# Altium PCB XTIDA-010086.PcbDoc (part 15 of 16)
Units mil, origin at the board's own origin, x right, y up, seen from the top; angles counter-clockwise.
Board outline 14763.78 x 8267.72 mil, 6 copper layers (Top Layer, GND Layer, Signal Layer 1, Signal Layer 2, Power Layer, Bottom Layer), stack 62 mil thick; 1933 components, 1002 nets, 4886 pads, 6482 vias.
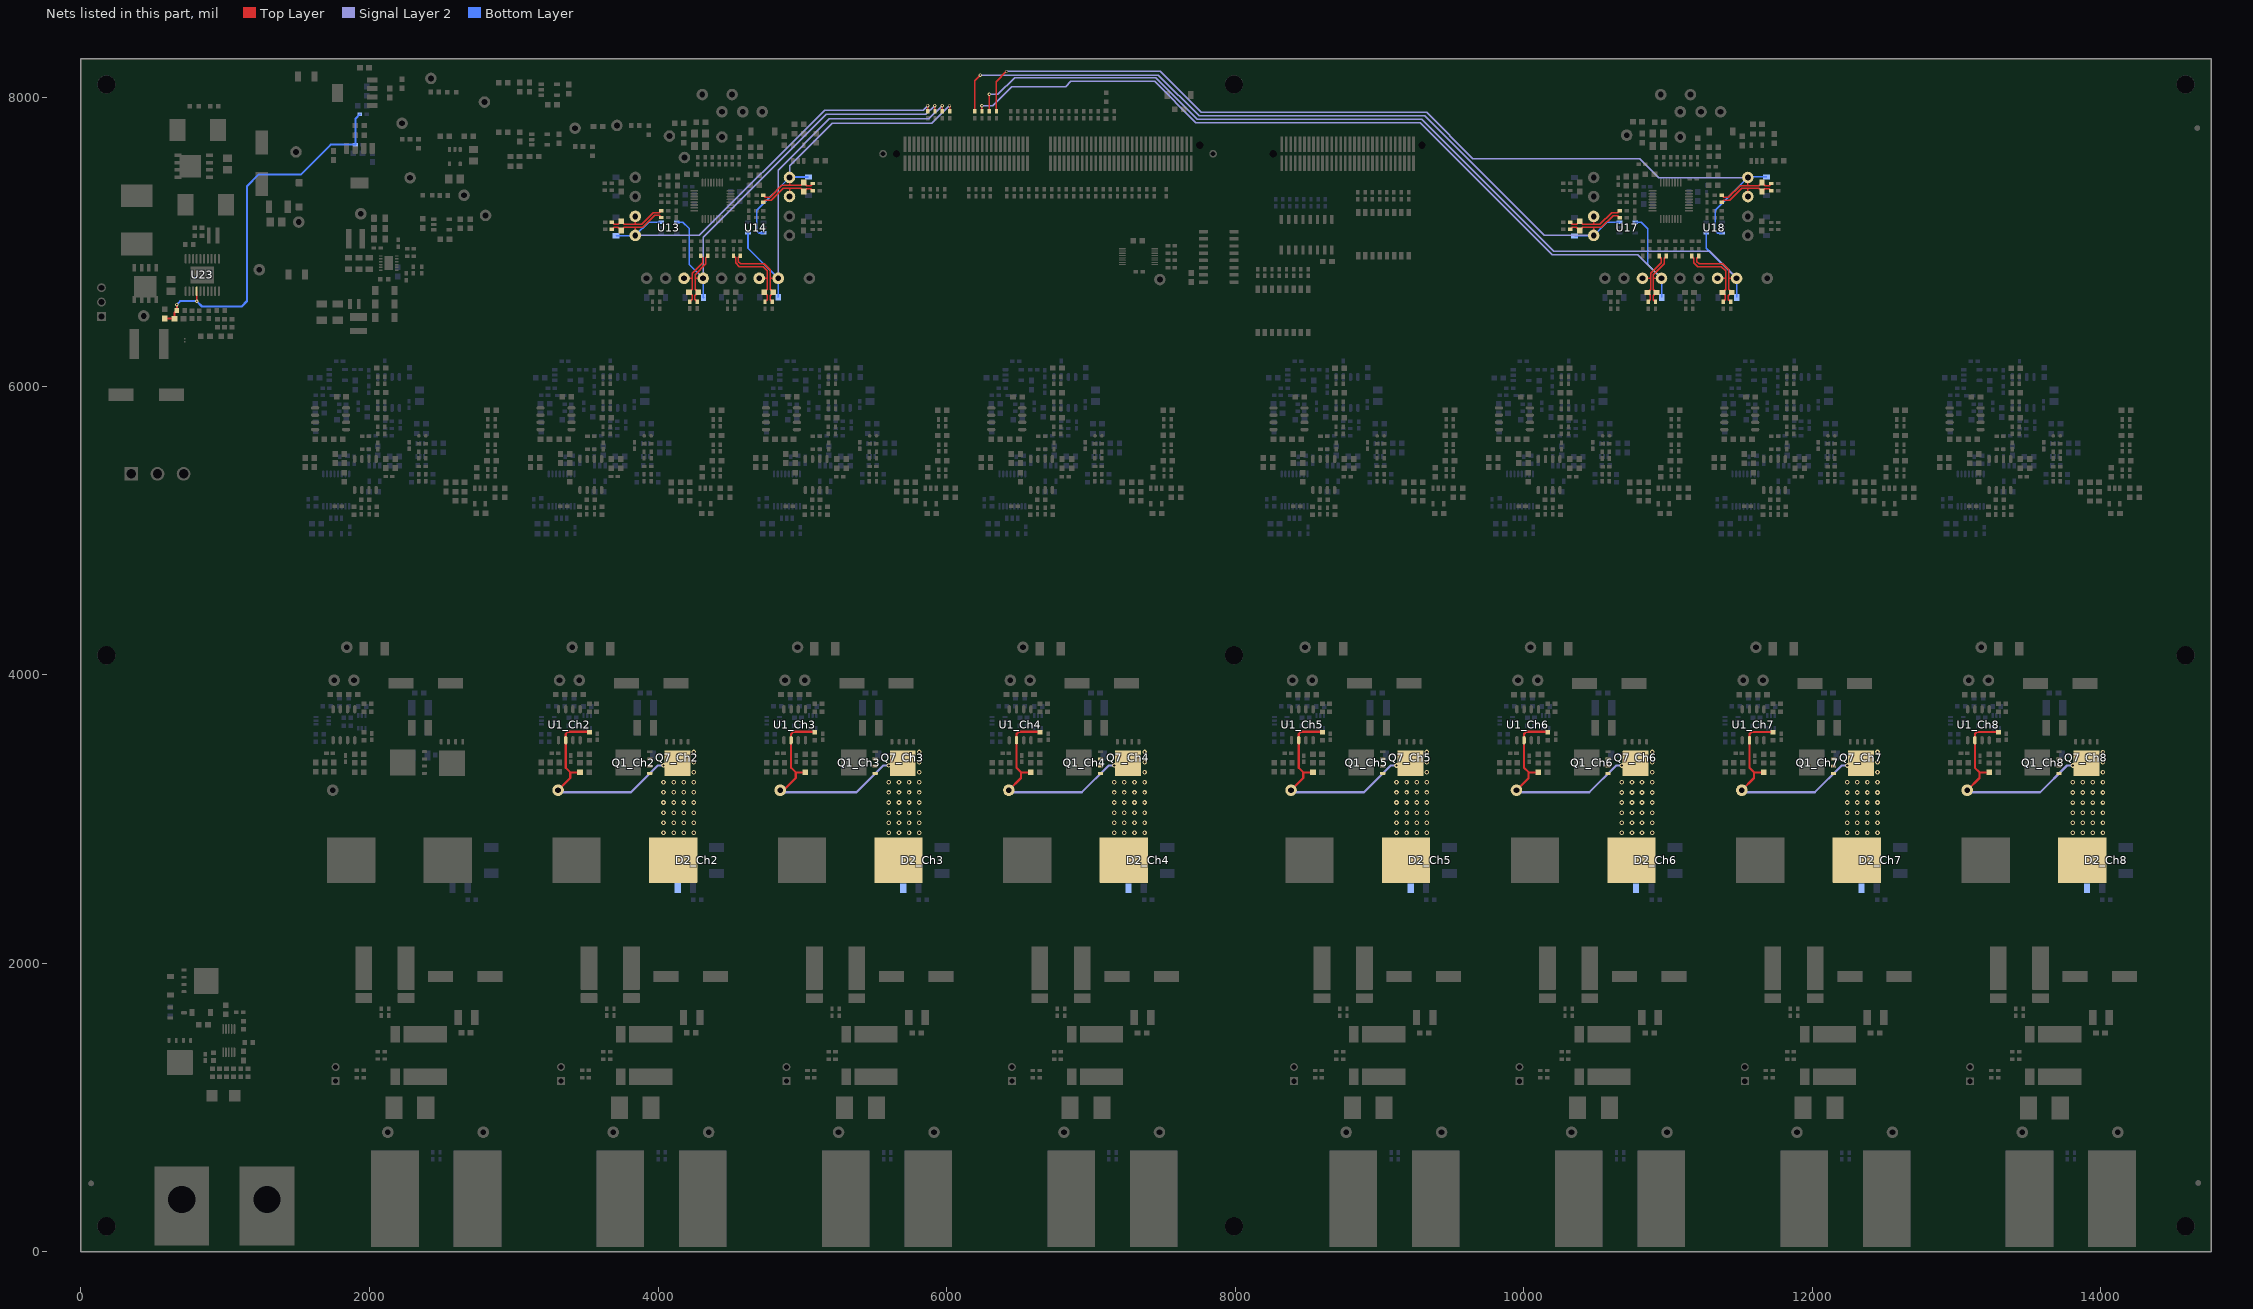
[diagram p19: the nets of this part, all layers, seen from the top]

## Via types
v1: diameter 32, hole 16, Top Layer to Bottom Layer, tented both sides, 4685 vias
v2: diameter 24, hole 12, Top Layer to Bottom Layer, tented both sides, 1013 vias
v3: diameter 32, hole 16, Top Layer to Bottom Layer, 728 vias
v4: diameter 19.68, hole 7.87, Top Layer to Bottom Layer, 40 vias
v5: diameter 214.57, hole 140, Top Layer to Bottom Layer, 16 vias

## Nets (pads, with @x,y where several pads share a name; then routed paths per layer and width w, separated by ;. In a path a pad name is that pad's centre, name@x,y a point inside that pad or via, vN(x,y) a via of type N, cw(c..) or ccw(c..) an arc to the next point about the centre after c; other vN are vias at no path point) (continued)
SW_Ch2: C1_Ch2.2 C2_Ch2.1 D2_Ch2.4 L2_Ch2.1 Q1_Ch2.1 Q1_Ch2.2 Q1_Ch2.3 Q7_Ch2.5 Q7_Ch2.6 Q7_Ch2.7 Q7_Ch2.8 Q7_Ch2.9@4134,3385.39 R9_Ch2.1 R18_Ch2.1 TP2_Ch2.1 U1_Ch2.6 | length 1490.1
  Top Layer w15: TP2_Ch2.1@3307.39,3199.23 3392.16,3283.99 3392.16,3322.99 ; R18_Ch2.1@3459.37,3322.99 3392.16,3322.99 ; C1_Ch2.2@3524.33,3601.79 3522.08,3604.04 3375.11,3604.04 3360.37,3589.29 U1_Ch2.6@3360.37,3545.71 3360.37,3354.78 3392.16,3322.99
  Signal Layer 2 w15: TP2_Ch2.1@3307.39,3199.23 3321.7,3184.92 3813,3184.92 3999,3370.92 v1(4038,3370.92)
  other v1: 4038,2903.92 4108,2903.92 4178,2903.92 4248,2903.92 4038,2973.92 4108,2973.92 4178,2973.92 4248,2973.92 4038,3043.92 4108,3043.92 4178,3043.92 4248,3043.92 4038,3113.92 4108,3113.92 4178,3113.92 4248,3113.92 4038,3183.92 4108,3183.92 4178,3183.92 4248,3183.92 4038,3253.92 4108,3253.92 4178,3253.92 4248,3253.92 4248,3323.92 4248,3393.92 4248,3463.92
SW_Ch3: C1_Ch3.2 C2_Ch3.1 D2_Ch3.4 L2_Ch3.1 Q1_Ch3.1 Q1_Ch3.2 Q1_Ch3.3 Q7_Ch3.5 Q7_Ch3.6 Q7_Ch3.7 Q7_Ch3.8 Q7_Ch3.9@5696,3385.31 R9_Ch3.1 R18_Ch3.1 TP2_Ch3.1 U1_Ch3.6 | length 1490.1
  Top Layer w15: TP2_Ch3.1@4869.39,3199.15 4954.16,3283.91 4954.16,3322.91 ; R18_Ch3.1@5021.37,3322.91 4954.16,3322.91 ; C1_Ch3.2@5086.33,3601.71 5084.08,3603.96 4937.11,3603.96 4922.37,3589.21 U1_Ch3.6@4922.37,3545.63 4922.37,3354.7 4954.16,3322.91
  Signal Layer 2 w15: TP2_Ch3.1@4869.39,3199.15 4883.7,3184.84 5375,3184.84 5561,3370.84 v1(5600,3370.84)
  other v1: 5600,2903.84 5670,2903.84 5740,2903.84 5810,2903.84 5600,2973.84 5670,2973.84 5740,2973.84 5810,2973.84 5600,3043.84 5670,3043.84 5740,3043.84 5810,3043.84 5600,3113.84 5670,3113.84 5740,3113.84 5810,3113.84 5600,3183.84 5670,3183.84 5740,3183.84 5810,3183.84 5600,3253.84 5670,3253.84 5740,3253.84 5810,3253.84 5810,3323.84 5810,3393.84 5810,3463.84
SW_Ch4: C1_Ch4.2 C2_Ch4.1 D2_Ch4.4 L2_Ch4.1 Q1_Ch4.1 Q1_Ch4.2 Q1_Ch4.3 Q7_Ch4.5 Q7_Ch4.6 Q7_Ch4.7 Q7_Ch4.8 Q7_Ch4.9@7258,3385.24 R9_Ch4.1 R18_Ch4.1 TP2_Ch4.1 U1_Ch4.6 | length 1490.1
  Top Layer w15: TP2_Ch4.1@6431.39,3199.07 6516.16,3283.83 6516.16,3322.83 ; R18_Ch4.1@6583.37,3322.83 6516.16,3322.83 ; C1_Ch4.2@6648.33,3601.63 6646.08,3603.88 6499.11,3603.88 6484.37,3589.14 U1_Ch4.6@6484.37,3545.55 6484.37,3354.62 6516.16,3322.83
  Signal Layer 2 w15: TP2_Ch4.1@6431.39,3199.07 6445.7,3184.76 6937,3184.76 7123,3370.76 v1(7162,3370.76)
  other v1: 7162,2903.76 7232,2903.76 7302,2903.76 7372,2903.76 7162,2973.76 7232,2973.76 7302,2973.76 7372,2973.76 7162,3043.76 7232,3043.76 7302,3043.76 7372,3043.76 7162,3113.76 7232,3113.76 7302,3113.76 7372,3113.76 7162,3183.76 7232,3183.76 7302,3183.76 7372,3183.76 7162,3253.76 7232,3253.76 7302,3253.76 7372,3253.76 7372,3323.76 7372,3393.76 7372,3463.76
SW_Ch5: C1_Ch5.2 C2_Ch5.1 D2_Ch5.4 L2_Ch5.1 Q1_Ch5.1 Q1_Ch5.2 Q1_Ch5.3 Q7_Ch5.5 Q7_Ch5.6 Q7_Ch5.7 Q7_Ch5.8 Q7_Ch5.9@9213.7,3385.16 R9_Ch5.1 R18_Ch5.1 TP2_Ch5.1 U1_Ch5.6 | length 1490.1
  Top Layer w15: TP2_Ch5.1@8387.09,3198.99 8471.86,3283.76 8471.86,3322.75 ; R18_Ch5.1@8539.07,3322.75 8471.86,3322.75 ; C1_Ch5.2@8604.03,3601.55 8601.78,3603.8 8454.81,3603.8 8440.07,3589.06 U1_Ch5.6@8440.07,3545.47 8440.07,3354.54 8471.86,3322.75
  Signal Layer 2 w15: TP2_Ch5.1@8387.09,3198.99 8401.4,3184.69 8892.7,3184.69 9078.7,3370.69 v1(9117.7,3370.69)
  other v1: 9117.7,2903.69 9187.7,2903.69 9257.7,2903.69 9327.7,2903.69 9117.7,2973.69 9187.7,2973.69 9257.7,2973.69 9327.7,2973.69 9117.7,3043.69 9187.7,3043.69 9257.7,3043.69 9327.7,3043.69 9117.7,3113.69 9187.7,3113.69 9257.7,3113.69 9327.7,3113.69 9117.7,3183.69 9187.7,3183.69 9257.7,3183.69 9327.7,3183.69 9117.7,3253.69 9187.7,3253.69 9257.7,3253.69 9327.7,3253.69 9327.7,3323.69 9327.7,3393.69 9327.7,3463.69
SW_Ch6: C1_Ch6.2 C2_Ch6.1 D2_Ch6.4 L2_Ch6.1 Q1_Ch6.1 Q1_Ch6.2 Q1_Ch6.3 Q7_Ch6.5 Q7_Ch6.6 Q7_Ch6.7 Q7_Ch6.8 Q7_Ch6.9@10775.7,3385.08 R9_Ch6.1 R18_Ch6.1 TP2_Ch6.1 U1_Ch6.6 | length 1490.1
  Top Layer w15: TP2_Ch6.1@9949.09,3198.91 10033.86,3283.68 10033.86,3322.68 ; R18_Ch6.1@10101.07,3322.68 10033.86,3322.68 ; C1_Ch6.2@10166.03,3601.47 10163.78,3603.72 10016.81,3603.72 10002.07,3588.98 U1_Ch6.6@10002.07,3545.39 10002.07,3354.46 10033.86,3322.68
  Signal Layer 2 w15: TP2_Ch6.1@9949.09,3198.91 9963.4,3184.61 10454.7,3184.61 10640.7,3370.61 v1(10679.7,3370.61)
  other v1: 10679.7,2903.61 10749.7,2903.61 10819.7,2903.61 10889.7,2903.61 10679.7,2973.61 10749.7,2973.61 10819.7,2973.61 10889.7,2973.61 10679.7,3043.61 10749.7,3043.61 10819.7,3043.61 10889.7,3043.61 10679.7,3113.61 10749.7,3113.61 10819.7,3113.61 10889.7,3113.61 10679.7,3183.61 10749.7,3183.61 10819.7,3183.61 10889.7,3183.61 10679.7,3253.61 10749.7,3253.61 10819.7,3253.61 10889.7,3253.61 10889.7,3323.61 10889.7,3393.61 10889.7,3463.61
SW_Ch7: C1_Ch7.2 C2_Ch7.1 D2_Ch7.4 L2_Ch7.1 Q1_Ch7.1 Q1_Ch7.2 Q1_Ch7.3 Q7_Ch7.5 Q7_Ch7.6 Q7_Ch7.7 Q7_Ch7.8 Q7_Ch7.9@12337.7,3385 R9_Ch7.1 R18_Ch7.1 TP2_Ch7.1 U1_Ch7.6 | length 1490.1
  Top Layer w15: TP2_Ch7.1@11511.09,3198.83 11595.86,3283.6 11595.86,3322.6 ; R18_Ch7.1@11663.07,3322.6 11595.86,3322.6 ; C1_Ch7.2@11728.03,3601.39 11725.78,3603.64 11578.81,3603.64 11564.07,3588.9 U1_Ch7.6@11564.07,3545.31 11564.07,3354.38 11595.86,3322.6
  Signal Layer 2 w15: TP2_Ch7.1@11511.09,3198.83 11525.4,3184.53 12016.7,3184.53 12202.7,3370.53 v1(12241.7,3370.53)
  other v1: 12241.7,2903.53 12311.7,2903.53 12381.7,2903.53 12451.7,2903.53 12241.7,2973.53 12311.7,2973.53 12381.7,2973.53 12451.7,2973.53 12241.7,3043.53 12311.7,3043.53 12381.7,3043.53 12451.7,3043.53 12241.7,3113.53 12311.7,3113.53 12381.7,3113.53 12451.7,3113.53 12241.7,3183.53 12311.7,3183.53 12381.7,3183.53 12451.7,3183.53 12241.7,3253.53 12311.7,3253.53 12381.7,3253.53 12451.7,3253.53 12451.7,3323.53 12451.7,3393.53 12451.7,3463.53
SW_Ch8: C1_Ch8.2 C2_Ch8.1 D2_Ch8.4 L2_Ch8.1 Q1_Ch8.1 Q1_Ch8.2 Q1_Ch8.3 Q7_Ch8.5 Q7_Ch8.6 Q7_Ch8.7 Q7_Ch8.8 Q7_Ch8.9@13899.7,3384.92 R9_Ch8.1 R18_Ch8.1 TP2_Ch8.1 U1_Ch8.6 | length 1490.1
  Top Layer w15: TP2_Ch8.1@13073.09,3198.76 13157.86,3283.52 13157.86,3322.52 ; R18_Ch8.1@13225.07,3322.52 13157.86,3322.52 ; C1_Ch8.2@13290.03,3601.31 13287.78,3603.56 13140.81,3603.56 13126.07,3588.82 U1_Ch8.6@13126.07,3545.23 13126.07,3354.31 13157.86,3322.52
  Signal Layer 2 w15: TP2_Ch8.1@13073.09,3198.76 13087.4,3184.45 13578.7,3184.45 13764.7,3370.45 v1(13803.7,3370.45)
  other v1: 13803.7,2903.45 13873.7,2903.45 13943.7,2903.45 14013.7,2903.45 13803.7,2973.45 13873.7,2973.45 13943.7,2973.45 14013.7,2973.45 13803.7,3043.45 13873.7,3043.45 13943.7,3043.45 14013.7,3043.45 13803.7,3113.45 13873.7,3113.45 13943.7,3113.45 14013.7,3113.45 13803.7,3183.45 13873.7,3183.45 13943.7,3183.45 14013.7,3183.45 13803.7,3253.45 13873.7,3253.45 13943.7,3253.45 14013.7,3253.45 14013.7,3323.45 14013.7,3393.45 14013.7,3463.45
UVLO: R188.1 R189.1 R206.1 R207.1 R208.2 U23.4 | length 2657.8
  Top Layer w12: v2(803.12,6588.34) U23.4@803.12,6657.5
  Top Layer w15: R207.1@581.5,6468.2 648.5,6468.2 R208.2@649.01,6467.7 649.01,6507.76 R206.1@665.94,6524.7 665.94,6563.76 v2(665,6564.7)
  Bottom Layer w15: v2(665,6564.7) 688.64,6588.34 v2(803.12,6588.34) 839.76,6551.7 1114.7,6551.7 1152,6589 1152,7385 1234,7467 1526.5,7467 1732.5,7673 R188.1@1903.38,7673 1903.38,7853 R189.1@1933.38,7883
"UVP: 10.4V": C59.2 R84.1 R88.2 U11.4 | length 219.5
  Top Layer w10: U11.4@1045.02,1383.07 1045.02,1336.98 1056.35,1325.65 1056.35,1310
  Top Layer w15: 1056.35,1310 1056.35,1269.32 1107.63,1269.32 R88.2@1107.83,1269.12 C59.2@1157.33,1269.12
VoutN1: C51_Ch1.2 R74_Ch1.2 R92.1 TP10_Ch1.1 | length 462.7
  Top Layer w10: R74_Ch1.2@3680.47,7136.14 3695.7,7120.91 3724.26,7120.91 C51_Ch1.2@3744.87,7141.52 3766.37,7120.03 3842.53,7120.03 ; TP10_Ch1.1@3842.53,7176.03 3842.53,7120.03 ; R92.1@4023.49,7216.33 4009.4,7202.24 3968.54,7202.24 3886.33,7120.03 3842.53,7120.03
VoutN2: C51_Ch2.2 R74_Ch2.2 R99.1 TP10_Ch2.1 | length 432.8
  Top Layer w10: TP10_Ch2.1@4180.68,6746.7 4235.68,6746.7 ; R74_Ch2.2@4220.57,6584.65 4235.8,6599.87 4235.8,6628.43 C51_Ch2.2@4215.18,6649.05 4236.68,6670.54 4236.68,6780.67 4311.65,6855.63 4311.65,6887.68 R99.1@4297.56,6901.77
VoutN3: C51_Ch3.2 R74_Ch3.2 R104.1 TP10_Ch3.1 | length 590.8
  Top Layer w10: R104.1@4523.3,6901.77 4537.3,6887.77 4537.3,6854.86 4564.45,6827.7 4728.47,6827.7 4757.1,6799.07 4757.1,6746.7 ; TP10_Ch3.1@4701.1,6746.7 4757.1,6746.7 ; R74_Ch3.2@4741.24,6583.71 4756.47,6598.94 4756.47,6628.18 C51_Ch3.2@4735.61,6649.05 4757.1,6670.54 4757.1,6746.7
VoutN4: C51_Ch4.2 R74_Ch4.2 R116.1 TP10_Ch4.1 | length 462.7
  Top Layer w10: R116.1@4730.36,7273.89 4744.45,7287.98 4785.31,7287.98 4867.53,7370.19 4911.32,7370.19 ; TP10_Ch4.1@4911.32,7314.19 4911.32,7370.19 ; C51_Ch4.2@5008.98,7348.14 5029.59,7368.75 5058.15,7368.75 R74_Ch4.2@5073.38,7353.52 ; C51_Ch4.2@5008.98,7348.7 4987.48,7370.19 4911.32,7370.19
VoutN5: C51_Ch5.2 R74_Ch5.2 R123.1 TP10_Ch5.1 | length 462.7
  Top Layer w10: R74_Ch5.2@10322.17,7135.82 10337.4,7120.59 10365.96,7120.59 C51_Ch5.2@10386.58,7141.21 10408.07,7119.71 10484.23,7119.71 ; TP10_Ch5.1@10484.23,7175.71 10484.23,7119.71 ; R123.1@10665.19,7216.02 10651.1,7201.93 10610.24,7201.93 10528.03,7119.71 10484.23,7119.71
VoutN6: C51_Ch6.2 R74_Ch6.2 R130.1 TP10_Ch6.1 | length 432.8
  Top Layer w10: TP10_Ch6.1@10822.38,6746.39 10877.38,6746.39 ; R74_Ch6.2@10862.27,6584.33 10877.5,6599.56 10877.5,6628.12 10861.89,6643.73 C51_Ch6.2@10856.89,6648.73 10878.38,6670.23 10878.38,6780.35 10953.35,6855.32 10953.35,6887.36 R130.1@10939.26,6901.45
VoutN7: C51_Ch7.2 R74_Ch7.2 R135.1 TP10_Ch7.1 | length 589.8
  Top Layer w10: R135.1@11165,6901.45 11179,6887.45 11179,6854.54 11206.15,6827.39 11370.17,6827.39 11398.8,6798.76 11398.8,6746.39 ; TP10_Ch7.1@11342.8,6746.39 11398.8,6746.39 ; R74_Ch7.2@11382.69,6584.33 11397.92,6599.56 11397.92,6628.12 11382.31,6643.73 C51_Ch7.2@11377.31,6648.73 11398.8,6670.23 11398.8,6746.39
VoutN8: C51_Ch8.2 R74_Ch8.2 R147.1 TP10_Ch8.1 | length 462.7
  Top Layer w10: R147.1@11372.06,7273.57 11386.15,7287.67 11427.01,7287.67 11509.23,7369.88 11553.02,7369.88 ; TP10_Ch8.1@11553.02,7313.88 11553.02,7369.88 ; C51_Ch8.2@11650.68,7347.82 11671.29,7368.44 11699.85,7368.44 R74_Ch8.2@11715.08,7353.21 ; C51_Ch8.2@11650.68,7348.38 11629.18,7369.88 11553.02,7369.88
VoutP1: C51_Ch1.1 D16.2 R68_Ch1.2 R93.1 R247.1 TP9_Ch1.1 U13.3 | length 3253.5
  Top Layer w10: R68_Ch1.2@3680.47,7085.68 3695.7,7100.91 3722.5,7100.91 C51_Ch1.1@3744.87,7078.53 3766.37,7100.03 3842,7100.03 ; TP9_Ch1.1@3842.53,7044.03 3842.53,7099.5 3842,7100.03 ; R93.1@4023.49,7168.15 4009.4,7182.24 3976.82,7182.24 3894.61,7100.03 3842,7100.03 ; R247.1@5868.74,7903.54 v2@5868.74,7944.26
  Signal Layer 2 w10: TP9_Ch1.1@3842.53,7044.03 4286.03,7044.03 5154,7912 5836.48,7912 v2(5868.06,7943.58)
  Bottom Layer w12: D16.2@3710,7041.53 3840.03,7041.53 TP9_Ch1.1@3842.53,7044.03 3934.6,7136.1 U13.3@4021.87,7136.1
VoutP2: C51_Ch2.1 D20.2 R68_Ch2.2 R100.1 R248.1 TP9_Ch2.1 U13.4 | length 3366.2
  Top Layer w10: R68_Ch2.2@4271.03,6584.65 4255.8,6599.87 4255.8,6626.67 C51_Ch2.1@4278.18,6649.05 4256.68,6670.54 4256.68,6746.7 ; TP9_Ch2.1@4312.68,6746.7 4256.68,6746.7 ; R100.1@4345.74,6901.77 4331.65,6887.68 4331.65,6847.35 4256.68,6772.38 4256.68,6746.7 ; R248.1@5919.39,7903.54 v2@5919.39,7944.26
  Signal Layer 2 w10: TP9_Ch2.1@4312.68,6746.7 4312.68,7029.68 5165,7882 5857.13,7882 v2(5918.71,7943.58)
  Bottom Layer w12: U13.4@4130.13,7136.1 4172.6,7136.1 4217,7091.7 4217,6842.38 TP9_Ch2.1@4312.68,6746.7 4312.68,6616.67 D20.2@4315.18,6614.17
VoutP3: C51_Ch3.1 D22.2 R68_Ch3.2 R107.1 R251.1 TP9_Ch3.1 U14.4 | length 3235.2
  Top Layer w10: R107.1@4571.3,6901.77 4557.3,6887.77 4557.3,6863.14 4572.74,6847.7 4736.76,6847.7 4777.1,6807.36 4777.1,6670.54 C51_Ch3.1@4798.6,6649.05 4776.47,6626.92 4776.47,6598.94 R68_Ch3.2@4791.7,6583.71 ; 4778.1,6746.7 TP9_Ch3.1@4833.1,6746.7 ; R251.1@5970.03,7903.54 v2@5970.03,7944.26
  Signal Layer 2 w10: TP9_Ch3.1@4833.1,6746.7 4833.1,7496.82 5188.28,7852 5877.78,7852 v2(5969.35,7943.58)
  Bottom Layer w12: U14.4@4623.72,7061.3 4623.72,6956.08 TP9_Ch3.1@4833.1,6746.7 4833.1,6616.11 D22.2@4833.67,6615.54
VoutP4: C51_Ch4.1 D24.2 R68_Ch4.2 R117.1 R252.1 TP9_Ch4.1 U14.3 | length 2515.6
  Top Layer w10: R117.1@4730.36,7322.07 4744.45,7307.98 4777.03,7307.98 4859.24,7390.19 4911.85,7390.19 ; TP9_Ch4.1@4911.32,7446.19 TP9_Ch4.1@4911.32,7445.63 4911.32,7390.72 4911.85,7390.19 ; C51_Ch4.1@5008.98,7411.13 5031.35,7388.75 5058.15,7388.75 R68_Ch4.2@5073.38,7403.98 ; C51_Ch4.1@5008.98,7411.69 4987.48,7390.19 4911.85,7390.19 ; R252.1@6020.68,7903.54 v2@6020.68,7944.26
  Signal Layer 2 w10: TP9_Ch4.1@4911.32,7445.63 4911.32,7525.32 5208,7822 5898.42,7822 v2(6020,7943.58)
  Bottom Layer w12: U14.3@4731.99,7061.3 4698.25,7061.3 4684.85,7074.7 4684.85,7219.16 TP9_Ch4.1@4911.32,7445.63 4915.19,7449.5 D24.2@5041.93,7449.5
VoutP5: C51_Ch5.1 D26.2 R68_Ch5.2 R124.1 R255.1 TP9_Ch5.1 U17.3 | length 5792.4
  Top Layer w10: R255.1@6194.68,7903.54 6194.68,8115.68 v2(6234,8155) ; R68_Ch5.2@10322.17,7085.37 10337.4,7100.59 10364.2,7100.59 C51_Ch5.1@10386.58,7078.22 10408.07,7099.71 10483.7,7099.71 ; TP9_Ch5.1@10484.23,7043.71 10484.23,7099.18 10483.7,7099.71 ; R124.1@10665.19,7167.84 10651.1,7181.93 10618.52,7181.93 10536.31,7099.71 10483.7,7099.71
  Signal Layer 2 w10: v2(6234,8155) 7468.51,8155 7750.51,7873 9312.7,7873 10141.99,7043.71 TP9_Ch5.1@10484.23,7043.71
  Bottom Layer w10: D26.2@10352.7,7040.22 10480.73,7040.22 TP9_Ch5.1@10484.23,7043.71
  Bottom Layer w12: TP9_Ch5.1@10484.23,7043.71 10576.3,7135.79 U17.3@10663.57,7135.79
VoutP6: C51_Ch6.1 D28.2 R68_Ch6.2 R131.1 R256.1 TP9_Ch6.1 U17.4 | length 6441.5
  Top Layer w10: v2(6244.73,7942.21) 6244.73,7903.82 R256.1@6245.01,7903.54 ; R68_Ch6.2@10912.73,6584.33 10897.5,6599.56 10897.5,6626.36 C51_Ch6.1@10919.88,6648.73 10898.38,6670.23 10898.38,6746.39 ; TP9_Ch6.1@10954.38,6746.39 10898.38,6746.39 ; R131.1@10987.44,6901.45 10973.35,6887.36 10973.35,6847.03 10898.38,6772.07 10898.38,6746.39
  Signal Layer 2 w10: v2(6244.73,7942.21) 6319.77,7942.21 6451.56,8074 6824,8074 6861,8111 7440.91,8111 7726.91,7825 9282,7825 10196,6911 10789.77,6911 TP9_Ch6.1@10954.38,6746.39
  Bottom Layer w10: TP9_Ch6.1@10954.38,6746.39 10956.88,6743.89 D28.2@10956.88,6613.86
  Bottom Layer w12: U17.4@10771.83,7135.79 10814.3,7135.79 10858.7,7091.39 10858.7,6842.07 TP9_Ch6.1@10954.38,6746.39
VoutP7: C51_Ch7.1 D30.2 R68_Ch7.2 R138.1 R259.1 TP9_Ch7.1 U18.4 | length 7043
  Top Layer w10: R259.1@6295.35,7903.54 6295.35,8018.67 6297,8020.32 v2(6297,8022) ; R138.1@11213,6901.45 11199,6887.45 11199,6862.83 11214.44,6847.39 11378.46,6847.39 11418.8,6807.04 11418.8,6670.23 C51_Ch7.1@11440.3,6648.73 11417.92,6626.36 11417.92,6599.56 R68_Ch7.2@11433.15,6584.33 ; 11419.8,6746.39 TP9_Ch7.1@11474.8,6746.39
  Signal Layer 2 w10: v2(6297,8022) 6356,8022 6471.13,8137.13 7448.87,8137.13 7736,7850 9292,7850 10208.13,6933.87 11287.31,6933.87 TP9_Ch7.1@11474.8,6746.39
  Bottom Layer w10: TP9_Ch7.1@11474.8,6746.39 11475.37,6745.82 D30.2@11475.37,6615.22
  Bottom Layer w12: U18.4@11265.42,7060.98 11265.42,6955.77 TP9_Ch7.1@11474.8,6746.39
VoutP8: C51_Ch8.1 D32.2 R68_Ch8.2 R148.1 R260.1 TP9_Ch8.1 U18.3 | length 6860.8
  Top Layer w10: R260.1@6345.68,7903.54 6345.68,8110.68 v2(6415,8180) ; R148.1@11372.06,7321.76 11386.15,7307.67 11418.73,7307.67 11500.94,7389.88 11553.55,7389.88 ; TP9_Ch8.1@11553.02,7445.88 TP9_Ch8.1@11553.02,7445.32 11553.02,7390.41 11553.55,7389.88 ; C51_Ch8.1@11650.68,7410.82 11673.05,7388.44 11699.85,7388.44 R68_Ch8.2@11715.08,7403.67 ; C51_Ch8.1@11650.68,7411.37 11629.18,7389.88 11553.55,7389.88
  Signal Layer 2 w10: v2(6415,8180) 7482,8180 7766,7896 9329,7896 9648,7577 10803,7577 10934.68,7445.32 TP9_Ch8.1@11553.02,7445.32
  Bottom Layer w10: TP9_Ch8.1@11553.02,7445.32 11556.89,7449.18 D32.2@11683.63,7449.18
  Bottom Layer w12: U18.3@11373.69,7060.98 11339.95,7060.98 11326.55,7074.39 11326.55,7218.85 TP9_Ch8.1@11553.02,7445.32
pads on no net: FID1.1 FID2.1 FID3.1 FID4.1 FID5.1 FID6.1 H1.1 H2.1 H3.1 H4.1 H5.1 H6.1 H7.0 H8.0 H9.0 H10.0 H11.0 H12.0 H13.1 H14.1 H15.0 H16.0 H17.1 H18.0 J5.1 J5.2 J5.3 J5.4 J5.5 J5.6 J5.8 J5.21 J5.23 J5.24 J5.25 J5.26 J5.27 J5.28 J5.30 J5.32 J5.41 J5.43 J5.44 J5.45 J5.66 J5.76 J5.78 J5.88 J5.89 J5.90 J5.91 J5.92 J5.93 J5.94 J5.95 J5.96 J5.100 J5.102 J5.104 J5.106 J5.107 J5.108 J5.109 J5.110 J5.113 J5.114 J5.115 J5.116 J5.117 J5.118 J5.119 J5.181 J5.182 J5.185 J5.186 J6.61 J6.62 J6.122 J6.124 J6.126 J6.128 J6.130 J6.132 J6.134 J6.136 J6.138 J6.139 J6.140 J6.141 J6.142 J6.143 J6.144 J6.145 J6.146 J6.147 J6.148 J6.149 J6.150 J6.151 J6.152 J6.153 J6.154 J6.155 J6.156 J6.159 J6.160 J6.161 J6.162 J6.163 J6.164 J6.165 J6.166 J6.167 J6.168 J6.169 J6.170 J6.171 J6.172 J6.173 J6.174 J6.175 J6.176 J6.177 J6.178 LBL1.0 Q1_Ch1.9@2215.84,3333.91 Q1_Ch1.9@2215.84,3391 Q1_Ch1.9@2215.84,3448.09 Q1_Ch1.9@2249.31,3391 Q1_Ch1.9@2285.92,3333.91 Q1_Ch1.9@2285.92,3391 Q1_Ch1.9@2285.92,3448.09 Q1_Ch2.9@3777.84,3333.83 Q1_Ch2.9@3777.84,3390.92 Q1_Ch2.9@3777.84,3448.01 Q1_Ch2.9@3811.31,3390.92 Q1_Ch2.9@3847.92,3333.83 Q1_Ch2.9@3847.92,3390.92 Q1_Ch2.9@3847.92,3448.01 Q1_Ch3.9@5339.84,3333.76 Q1_Ch3.9@5339.84,3390.84 Q1_Ch3.9@5339.84,3447.93 Q1_Ch3.9@5373.31,3390.84 Q1_Ch3.9@5409.92,3333.76 Q1_Ch3.9@5409.92,3390.84 Q1_Ch3.9@5409.92,3447.93 Q1_Ch4.9@6901.84,3333.68 Q1_Ch4.9@6901.84,3390.76 Q1_Ch4.9@6901.84,3447.85 Q1_Ch4.9@6935.31,3390.76 Q1_Ch4.9@6971.92,3333.68 Q1_Ch4.9@6971.92,3390.76 Q1_Ch4.9@6971.92,3447.85 Q1_Ch5.9@8857.54,3333.6 Q1_Ch5.9@8857.54,3390.69 Q1_Ch5.9@8857.54,3447.77 Q1_Ch5.9@8891.01,3390.69 Q1_Ch5.9@8927.62,3333.6 Q1_Ch5.9@8927.62,3390.69 Q1_Ch5.9@8927.62,3447.77 Q1_Ch6.9@10419.54,3333.52 Q1_Ch6.9@10419.54,3390.61 Q1_Ch6.9@10419.54,3447.69 Q1_Ch6.9@10453.01,3390.61 Q1_Ch6.9@10489.62,3333.52 Q1_Ch6.9@10489.62,3390.61 Q1_Ch6.9@10489.62,3447.69 Q1_Ch7.9@11981.54,3333.44 Q1_Ch7.9@11981.54,3390.53 Q1_Ch7.9@11981.54,3447.61 Q1_Ch7.9@12015.01,3390.53 Q1_Ch7.9@12051.62,3333.44 Q1_Ch7.9@12051.62,3390.53 Q1_Ch7.9@12051.62,3447.61 Q1_Ch8.9@13543.54,3333.36 Q1_Ch8.9@13543.54,3390.45 Q1_Ch8.9@13543.54,3447.54 Q1_Ch8.9@13577.01,3390.45 Q1_Ch8.9@13613.62,3333.36 Q1_Ch8.9@13613.62,3390.45 Q1_Ch8.9@13613.62,3447.54 Q2.9@818.86,1820.13 Q2.9@818.86,1878 Q2.9@818.86,1935.87 Q2.9@885,1820.13 Q2.9@885,1878 Q2.9@885,1935.87 Q3.9@628.46,1295.48 Q3.9@628.46,1361.62 Q3.9@686.33,1295.48 Q3.9@686.33,1361.62 Q3.9@744.2,1295.48 Q3.9@744.2,1361.62 Q7_Ch1.9@2514.91,3369.92 Q7_Ch1.9@2514.91,3440 Q7_Ch1.9@2572,3369.92 Q7_Ch1.9@2572,3403.39 Q7_Ch1.9@2572,3440 Q7_Ch1.9@2629.09,3369.92 Q7_Ch1.9@2629.09,3440 Q7_Ch2.9@4076.91,3369.84 Q7_Ch2.9@4076.91,3439.92 Q7_Ch2.9@4134,3369.84 Q7_Ch2.9@4134,3403.31 Q7_Ch2.9@4134,3439.92 Q7_Ch2.9@4191.09,3369.84 Q7_Ch2.9@4191.09,3439.92 Q7_Ch3.9@5638.91,3369.76 Q7_Ch3.9@5638.91,3439.84 Q7_Ch3.9@5696,3369.76 Q7_Ch3.9@5696,3403.23 Q7_Ch3.9@5696,3439.84 Q7_Ch3.9@5753.09,3369.76 Q7_Ch3.9@5753.09,3439.84 Q7_Ch4.9@7200.91,3369.69 Q7_Ch4.9@7200.91,3439.76 Q7_Ch4.9@7258,3369.69 Q7_Ch4.9@7258,3403.15 Q7_Ch4.9@7258,3439.76 Q7_Ch4.9@7315.09,3369.69 Q7_Ch4.9@7315.09,3439.76 Q7_Ch5.9@9156.61,3369.61 Q7_Ch5.9@9156.61,3439.69 Q7_Ch5.9@9213.7,3369.61 Q7_Ch5.9@9213.7,3403.07 Q7_Ch5.9@9213.7,3439.69 Q7_Ch5.9@9270.79,3369.61 Q7_Ch5.9@9270.79,3439.69 Q7_Ch6.9@10718.61,3369.53 Q7_Ch6.9@10718.61,3439.61 Q7_Ch6.9@10775.7,3369.53 Q7_Ch6.9@10775.7,3402.99 Q7_Ch6.9@10775.7,3439.61 Q7_Ch6.9@10832.79,3369.53 Q7_Ch6.9@10832.79,3439.61 Q7_Ch7.9@12280.61,3369.45 Q7_Ch7.9@12280.61,3439.53 Q7_Ch7.9@12337.7,3369.45 Q7_Ch7.9@12337.7,3402.91 Q7_Ch7.9@12337.7,3439.53 Q7_Ch7.9@12394.79,3369.45 Q7_Ch7.9@12394.79,3439.53 Q7_Ch8.9@13842.61,3369.37 Q7_Ch8.9@13842.61,3439.45 Q7_Ch8.9@13899.7,3369.37 Q7_Ch8.9@13899.7,3402.83 Q7_Ch8.9@13899.7,3439.45 Q7_Ch8.9@13956.79,3369.37 Q7_Ch8.9@13956.79,3439.45 S3.3 SH-J4.0 U7.4 U12.22 U16.22 U20.4 U21.13@2134,6826 U21.13@2134,6877.97 U22.2 U23.11 U26.14 U26.15 U27.14 U27.15 U28.15 U31.2

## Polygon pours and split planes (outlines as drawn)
PGND on Top Layer "PGND_L01_P679" (solid, remove dead copper, pour order 679): 1550,8206 1550,7568.7 1472,7490.7 1472,5123 1328,4979 77,4979 38,5018 38,8187 81,8230 1526,8230
AGND on Top Layer "AGND_L01_P673" (solid, remove dead copper, pour order 673): 51 vertices, not listed, extent 1518,4884 14680,8230
DGND on Top Layer "DGND_L01_P671" (solid, remove dead copper, pour order 671): 43 vertices, not listed, extent 1590,6299.47 11480,8230
12V_Out on Top Layer "12V_OUT_L01_P669" (solid, remove dead copper, pour order 669): 89 vertices, not listed, extent 450,1686 13318.12,5485
-5V on Top Layer "-5V_L01_P665" (solid, remove dead copper, pour order 665): 30 vertices, not listed, extent 1885,6943 2468.47,7296
12V_IN on Top Layer "12V_IN_L01_P663" (solid, remove dead copper, pour order 663): 45 vertices, not listed, extent 185,5324 1883,6766.7
AGND on Top Layer "AGND_L01_P661" (solid, remove dead copper, pour order 661): 35 vertices, not listed, extent 1612,6317 2358,7193
NetC104_2 on Top Layer "NETC104_2_L01_P655" (solid, remove dead copper, pour order 655): 19 vertices, not listed, extent 1817,6867 2093,7106
NetC104_1 on Top Layer "NETC104_1_L01_P653" (solid, remove dead copper, pour order 653): 1823,6783 1827,6779 2022,6779 2028,6785 2028,6810 2034,6816 2090,6816 2092,6818 2092,6829 2090,6831 1826,6831 1823,6828
NetC152_1 on Top Layer "NETC152_1_L01_P651" (solid, remove dead copper, pour order 651): 23 vertices, not listed, extent 1862,6442 2090,6808
DGND on Top Layer "DGND_L01_P646" (solid, remove dead copper, pour order 646): 17 vertices, not listed, extent 1738.41,7860 2168,8229
5V_D on Top Layer "5V_D_L01_P636" (solid, remove dead copper, pour order 636): 2487,8166.46 2470.46,8183 2198.56,8183 2185,8169.44 2185,8112 2192,8105 2356,8105 2383.49,8077.51 2482.51,8077.51 2487,8082
NetC141_1 on Top Layer "NETC141_1_L01_P634" (solid, remove dead copper, pour order 634): 2254.37,8078.13 2254.37,8045.37 2248,8039 1981,8039 1975,8045 1975,8083 2249.5,8083
no net on Top Layer "NONET_L01_P632" (solid, remove dead copper, pour order 632): 2122,8082
10V on Top Layer "10V_L01_P630" (solid, remove dead copper, pour order 630): 1974,8222.41 1981.59,8230 2095,8230 2103.69,8221.31 2103.69,8111.69 2095,8103 1978,8103 1974,8107
no net on Top Layer "NONET_L01_P628" (solid, remove dead copper, pour order 628): 1978,8117
no net on Top Layer "NONET_L01_P626" (solid, remove dead copper, pour order 626): 1980,8111
AGND on Top Layer "AGND_L01_P624" (solid, remove dead copper, pour order 624): 21 vertices, not listed, extent 1721,7366.56 2161,7759
NetC108_1 on Top Layer "NETC108_1_L01_P620" (solid, remove dead copper, pour order 620): 1878,7825.04 1882.96,7830 1921,7830 1925,7826 1925,7610 1920,7605 1883,7605 1878,7610
NetC138_1 on Top Layer "NETC138_1_L01_P584" (solid, remove dead copper, pour order 584): 3147.46,8131.54 3211.46,8131.54 3218,8125 3218,8082 3215,8079 3148,8079 2943.46,8079 2938,8084.46 2938,8125 2944.54,8131.54
DVDD on Top Layer "DVDD_L01_P578" (solid, remove dead copper, pour order 578): 9229.51,7335 9221.51,7327 8837.21,7327 8829.51,7334.7 8829.51,7402 8835.51,7408 9224.64,7408 9229.51,7403.12
DVDD on Top Layer "DVDD_L01_P572" (solid, remove dead copper, pour order 572): 8533,6803 8525,6795 8140.7,6795 8133,6802.7 8133,6870 8139,6876 8528.12,6876 8533,6871.12
PGND on Top Layer "PGND_L01_P460" (solid, remove dead copper, pour order 460): 25 vertices, not listed, extent 13706.2,33.45 14390.7,4231.45
NetF1_Ch8_1 on Top Layer "NETF1_CH8_1_L01_P468" (solid, remove dead copper, pour order 468): 13558.7,1077.45 13561.7,1074.45 13561.7,886.45 13691.7,756.45 13691.7,51.45 13673.7,33.45 13014.7,33.45 13000.7,47.45 13000.7,1067.45 13010.7,1077.45
NetF1_Ch8_2 on Top Layer "NETF1_CH8_2_L01_P472" (solid, remove dead copper, pour order 472): 13563.7,1119.45 13572.7,1110.45 13637.7,1110.45 13648.7,1099.45 13648.7,862.45 13680.7,830.45 13948.7,830.45 13961.7,843.45 13961.7,1281.45 13951.7,1291.45 13578.7,1291.45 13563.7,1276.45
NetC3_Ch8_1 on Top Layer "NETC3_CH8_1_L01_P476" (solid, remove dead copper, pour order 476): 13398.13,3265.02 13409.7,3253.45 13637.7,3253.45 13646.7,3262.45 13646.7,4221.45 13636.7,4231.45 13405.7,4231.45 13398.13,4223.87
SW_Ch8 on Top Layer "SW_CH8_L01_P480" (solid, remove dead copper, pour order 480): 13804.7,3481.45 13753.7,3430.45 13695.7,3430.45 13686.7,3421.45 13686.7,2558.97 13693.23,2552.45 14036.7,2552.45 14043.7,2559.45 14043.7,3471.21 14033.47,3481.45
NetL2_Ch8_2 on Top Layer "NETL2_CH8_2_L01_P484" (solid, remove dead copper, pour order 484): 13014.83,2889.45 13000.7,2875.32 13000.7,1823.45 13011.7,1812.45 13346.7,1812.45 13354.7,1820.45 13354.7,2111.45 13389.7,2146.45 13389.7,2882.45 13382.7,2889.45
NetC9_Ch8_1 on Top Layer "NETC9_CH8_1_L01_P488" (solid, remove dead copper, pour order 488): 17 vertices, not listed, extent 13513.7,1442.45 13984.7,2213.45
NetC9_Ch7_1 on Top Layer "NETC9_CH7_1_L01_P487" (solid, remove dead copper, pour order 487): 17 vertices, not listed, extent 11951.7,1442.53 12422.7,2213.53
NetL2_Ch7_2 on Top Layer "NETL2_CH7_2_L01_P483" (solid, remove dead copper, pour order 483): 11452.83,2889.53 11438.7,2875.4 11438.7,1823.53 11449.7,1812.53 11784.7,1812.53 11792.7,1820.53 11792.7,2111.53 11827.7,2146.53 11827.7,2882.53 11820.7,2889.53
SW_Ch7 on Top Layer "SW_CH7_L01_P479" (solid, remove dead copper, pour order 479): 12242.7,3481.53 12191.7,3430.53 12133.7,3430.53 12124.7,3421.53 12124.7,2559.05 12131.23,2552.53 12474.7,2552.53 12481.7,2559.53 12481.7,3471.29 12471.47,3481.53
NetC3_Ch7_1 on Top Layer "NETC3_CH7_1_L01_P475" (solid, remove dead copper, pour order 475): 11836.13,3265.1 11847.7,3253.53 12075.7,3253.53 12084.7,3262.53 12084.7,4221.53 12074.7,4231.53 11843.7,4231.53 11836.13,4223.95
NetF1_Ch7_2 on Top Layer "NETF1_CH7_2_L01_P471" (solid, remove dead copper, pour order 471): 12001.7,1119.53 12010.7,1110.53 12075.7,1110.53 12086.7,1099.53 12086.7,862.53 12118.7,830.53 12386.7,830.53 12399.7,843.53 12399.7,1281.53 12389.7,1291.53 12016.7,1291.53 12001.7,1276.53
NetF1_Ch7_1 on Top Layer "NETF1_CH7_1_L01_P467" (solid, remove dead copper, pour order 467): 11996.7,1077.53 11999.7,1074.53 11999.7,886.53 12129.7,756.53 12129.7,51.53 12111.7,33.53 11452.7,33.53 11438.7,47.53 11438.7,1067.53 11448.7,1077.53
PGND on Top Layer "PGND_L01_P459" (solid, remove dead copper, pour order 459): 25 vertices, not listed, extent 12144.2,33.53 12828.7,4231.53
2P5V on Top Layer "2P5V_L01_P518" (solid, remove dead copper, pour order 518): 2599.3,7411.32 2599.3,7286.02 2608,7277.32 2691,7277.32 2701,7287.32 2701,7473.32 2667,7507.32 2667,7548.32 2657,7558.32 2622.87,7558.32 2616,7551.45 2616,7494.32 2600,7478.32
-2P5V on Top Layer "-2P5V_L01_P514" (solid, remove dead copper, pour order 514): 2542,7134.7 2528,7148.7 2528,7222.7 2536,7230.7 2855.3,7230.7 2863,7223 2863,7144 2853.7,7134.7
PGND on Top Layer "PGND_L01_P458" (solid, remove dead copper, pour order 458): 25 vertices, not listed, extent 10582.2,33.61 11266.7,4231.61
NetF1_Ch6_1 on Top Layer "NETF1_CH6_1_L01_P466" (solid, remove dead copper, pour order 466): 10434.7,1077.61 10437.7,1074.61 10437.7,886.61 10567.7,756.61 10567.7,51.61 10549.7,33.61 9890.7,33.61 9876.7,47.61 9876.7,1067.61 9886.7,1077.61
NetF1_Ch6_2 on Top Layer "NETF1_CH6_2_L01_P470" (solid, remove dead copper, pour order 470): 10439.7,1119.61 10448.7,1110.61 10513.7,1110.61 10524.7,1099.61 10524.7,862.61 10556.7,830.61 10824.7,830.61 10837.7,843.61 10837.7,1281.61 10827.7,1291.61 10454.7,1291.61 10439.7,1276.61
NetC3_Ch6_1 on Top Layer "NETC3_CH6_1_L01_P474" (solid, remove dead copper, pour order 474): 10274.13,3265.18 10285.7,3253.61 10513.7,3253.61 10522.7,3262.61 10522.7,4221.61 10512.7,4231.61 10281.7,4231.61 10274.13,4224.03
SW_Ch6 on Top Layer "SW_CH6_L01_P478" (solid, remove dead copper, pour order 478): 10680.7,3481.61 10629.7,3430.61 10571.7,3430.61 10562.7,3421.61 10562.7,2559.13 10569.23,2552.61 10912.7,2552.61 10919.7,2559.61 10919.7,3471.37 10909.47,3481.61
NetL2_Ch6_2 on Top Layer "NETL2_CH6_2_L01_P482" (solid, remove dead copper, pour order 482): 9890.83,2889.61 9876.7,2875.48 9876.7,1823.61 9887.7,1812.61 10222.7,1812.61 10230.7,1820.61 10230.7,2111.61 10265.7,2146.61 10265.7,2882.61 10258.7,2889.61
NetC9_Ch6_1 on Top Layer "NETC9_CH6_1_L01_P486" (solid, remove dead copper, pour order 486): 17 vertices, not listed, extent 10389.7,1442.61 10860.7,2213.61
NetC9_Ch5_1 on Top Layer "NETC9_CH5_1_L01_P485" (solid, remove dead copper, pour order 485): 17 vertices, not listed, extent 8827.7,1442.69 9298.7,2213.69
NetL2_Ch5_2 on Top Layer "NETL2_CH5_2_L01_P481" (solid, remove dead copper, pour order 481): 8328.83,2889.68 8314.7,2875.56 8314.7,1823.69 8325.7,1812.69 8660.7,1812.69 8668.7,1820.69 8668.7,2111.69 8703.7,2146.68 8703.7,2882.69 8696.7,2889.69
SW_Ch5 on Top Layer "SW_CH5_L01_P477" (solid, remove dead copper, pour order 477): 9118.7,3481.69 9067.7,3430.69 9009.7,3430.69 9000.7,3421.69 9000.7,2559.21 9007.23,2552.69 9350.7,2552.69 9357.7,2559.69 9357.7,3471.45 9347.47,3481.69
NetC3_Ch5_1 on Top Layer "NETC3_CH5_1_L01_P473" (solid, remove dead copper, pour order 473): 8712.13,3265.26 8723.7,3253.69 8951.7,3253.69 8960.7,3262.69 8960.7,4221.69 8950.7,4231.69 8719.7,4231.69 8712.13,4224.11
NetF1_Ch5_2 on Top Layer "NETF1_CH5_2_L01_P469" (solid, remove dead copper, pour order 469): 8877.7,1119.69 8886.7,1110.69 8951.7,1110.69 8962.7,1099.69 8962.7,862.69 8994.7,830.69 9262.7,830.69 9275.7,843.69 9275.7,1281.69 9265.7,1291.69 8892.7,1291.69 8877.7,1276.69
NetF1_Ch5_1 on Top Layer "NETF1_CH5_1_L01_P465" (solid, remove dead copper, pour order 465): 8872.7,1077.69 8875.7,1074.69 8875.7,886.69 9005.7,756.69 9005.7,51.69 8987.7,33.69 8328.7,33.69 8314.7,47.69 8314.7,1067.69 8324.7,1077.69
PGND on Top Layer "PGND_L01_P457" (solid, remove dead copper, pour order 457): 25 vertices, not listed, extent 9020.2,33.69 9704.7,4231.69
NetF1_Ch4_1 on Top Layer "NETF1_CH4_1_L01_P404" (solid, remove dead copper, pour order 404): 6917,1077.76 6920,1074.76 6920,886.76 7050,756.76 7050,51.76 7032,33.76 6373,33.76 6359,47.76 6359,1067.76 6369,1077.76
NetF1_Ch4_2 on Top Layer "NETF1_CH4_2_L01_P412" (solid, remove dead copper, pour order 412): 6922,1119.76 6931,1110.76 6996,1110.76 7007,1099.76 7007,862.76 7039,830.76 7307,830.76 7320,843.76 7320,1281.76 7310,1291.76 6937,1291.76 6922,1276.76
NetC3_Ch4_1 on Top Layer "NETC3_CH4_1_L01_P420" (solid, remove dead copper, pour order 420): 6756.43,3265.34 6768,3253.76 6996,3253.76 7005,3262.76 7005,4221.76 6995,4231.76 6764,4231.76 6756.43,4224.19
SW_Ch4 on Top Layer "SW_CH4_L01_P428" (solid, remove dead copper, pour order 428): 7163,3481.76 7112,3430.76 7054,3430.76 7045,3421.76 7045,2559.29 7051.53,2552.76 7395,2552.76 7402,2559.76 7402,3471.53 7391.77,3481.76
NetL2_Ch4_2 on Top Layer "NETL2_CH4_2_L01_P436" (solid, remove dead copper, pour order 436): 6373.13,2889.76 6359,2875.64 6359,1823.76 6370,1812.76 6705,1812.76 6713,1820.76 6713,2111.76 6748,2146.76 6748,2882.76 6741,2889.76
NetC9_Ch4_1 on Top Layer "NETC9_CH4_1_L01_P444" (solid, remove dead copper, pour order 444): 17 vertices, not listed, extent 6872,1442.76 7343,2213.76
PGND on Top Layer "PGND_L01_P452" (solid, remove dead copper, pour order 452): 25 vertices, not listed, extent 7064.5,33.76 7749,4231.76
PGND on Top Layer "PGND_L01_P451" (solid, remove dead copper, pour order 451): 25 vertices, not listed, extent 5502.5,33.84 6187,4231.84
NetC9_Ch3_1 on Top Layer "NETC9_CH3_1_L01_P443" (solid, remove dead copper, pour order 443): 17 vertices, not listed, extent 5310,1442.84 5781,2213.84
NetL2_Ch3_2 on Top Layer "NETL2_CH3_2_L01_P435" (solid, remove dead copper, pour order 435): 4811.13,2889.84 4797,2875.71 4797,1823.84 4808,1812.84 5143,1812.84 5151,1820.84 5151,2111.84 5186,2146.84 5186,2882.84 5179,2889.84
SW_Ch3 on Top Layer "SW_CH3_L01_P427" (solid, remove dead copper, pour order 427): 5601,3481.84 5550,3430.84 5492,3430.84 5483,3421.84 5483,2559.37 5489.53,2552.84 5833,2552.84 5840,2559.84 5840,3471.61 5829.77,3481.84
NetC3_Ch3_1 on Top Layer "NETC3_CH3_1_L01_P419" (solid, remove dead copper, pour order 419): 5194.43,3265.42 5206,3253.84 5434,3253.84 5443,3262.84 5443,4221.84 5433,4231.84 5202,4231.84 5194.43,4224.27
NetF1_Ch3_2 on Top Layer "NETF1_CH3_2_L01_P411" (solid, remove dead copper, pour order 411): 5360,1119.84 5369,1110.84 5434,1110.84 5445,1099.84 5445,862.84 5477,830.84 5745,830.84 5758,843.84 5758,1281.84 5748,1291.84 5375,1291.84 5360,1276.84
NetF1_Ch3_1 on Top Layer "NETF1_CH3_1_L01_P403" (solid, remove dead copper, pour order 403): 5355,1077.84 5358,1074.84 5358,886.84 5488,756.84 5488,51.84 5470,33.84 4811,33.84 4797,47.84 4797,1067.84 4807,1077.84
NetF1_Ch2_1 on Top Layer "NETF1_CH2_1_L01_P402" (solid, remove dead copper, pour order 402): 3793,1077.92 3796,1074.92 3796,886.92 3926,756.92 3926,51.92 3908,33.92 3249,33.92 3235,47.92 3235,1067.92 3245,1077.92
NetF1_Ch2_2 on Top Layer "NETF1_CH2_2_L01_P410" (solid, remove dead copper, pour order 410): 3798,1119.92 3807,1110.92 3872,1110.92 3883,1099.92 3883,862.92 3915,830.92 4183,830.92 4196,843.92 4196,1281.92 4186,1291.92 3813,1291.92 3798,1276.92
NetC3_Ch2_1 on Top Layer "NETC3_CH2_1_L01_P418" (solid, remove dead copper, pour order 418): 3632.43,3265.5 3644,3253.92 3872,3253.92 3881,3262.92 3881,4221.92 3871,4231.92 3640,4231.92 3632.43,4224.35
SW_Ch2 on Top Layer "SW_CH2_L01_P426" (solid, remove dead copper, pour order 426): 4039,3481.92 3988,3430.92 3930,3430.92 3921,3421.92 3921,2559.45 3927.53,2552.92 4271,2552.92 4278,2559.92 4278,3471.69 4267.77,3481.92
NetL2_Ch2_2 on Top Layer "NETL2_CH2_2_L01_P434" (solid, remove dead copper, pour order 434): 3249.13,2889.92 3235,2875.79 3235,1823.92 3246,1812.92 3581,1812.92 3589,1820.92 3589,2111.92 3624,2146.92 3624,2882.92 3617,2889.92
NetC9_Ch2_1 on Top Layer "NETC9_CH2_1_L01_P442" (solid, remove dead copper, pour order 442): 17 vertices, not listed, extent 3748,1442.92 4219,2213.92
PGND on Top Layer "PGND_L01_P450" (solid, remove dead copper, pour order 450): 25 vertices, not listed, extent 3940.5,33.92 4625,4231.92
PGND on Top Layer "PGND_L01_P449" (solid, remove dead copper, pour order 449): 25 vertices, not listed, extent 2378.5,34 3063,4232
NetC9_Ch1_1 on Top Layer "NETC9_CH1_1_L01_P441" (solid, remove dead copper, pour order 441): 17 vertices, not listed, extent 2186,1443 2657,2214
NetL2_Ch1_2 on Top Layer "NETL2_CH1_2_L01_P433" (solid, remove dead copper, pour order 433): 1687.13,2890 1673,2875.87 1673,1824 1684,1813 2019,1813 2027,1821 2027,2112 2062,2147 2062,2883 2055,2890
SW_Ch1 on Top Layer "SW_CH1_L01_P425" (solid, remove dead copper, pour order 425): 2477,3482 2426,3431 2368,3431 2359,3422 2359,2559.53 2365.53,2553 2709,2553 2716,2560 2716,3471.77 2705.77,3482
NetC3_Ch1_1 on Top Layer "NETC3_CH1_1_L01_P417" (solid, remove dead copper, pour order 417): 2070.43,3265.57 2082,3254 2310,3254 2319,3263 2319,4222 2309,4232 2078,4232 2070.43,4224.43
NetF1_Ch1_2 on Top Layer "NETF1_CH1_2_L01_P409" (solid, remove dead copper, pour order 409): 2236,1120 2245,1111 2310,1111 2321,1100 2321,863 2353,831 2621,831 2634,844 2634,1282 2624,1292 2251,1292 2236,1277
NetF1_Ch1_1 on Top Layer "NETF1_CH1_1_L01_P401" (solid, remove dead copper, pour order 401): 2231,1078 2234,1075 2234,887 2364,757 2364,52 2346,34 1687,34 1673,48 1673,1068 1683,1078
DGND on Top Layer "DGND_L01_P400" (solid, remove dead copper, pour order 400): 8528.69,6420.97 8538.69,6410.97 8538.69,6304.97 8527.69,6293.97 8109.69,6293.97 8103.69,6299.97 8103.69,6414.97 8109.69,6420.97
DGND on Top Layer "DGND_L01_P399" (solid, remove dead copper, pour order 399): 9225.2,6952.97 9235.2,6942.97 9235.21,6836.97 9224.21,6825.97 8806.2,6825.97 8800.2,6831.97 8800.2,6946.97 8806.2,6952.97
DVDD on Top Layer "DVDD_L01_P395" (solid, remove dead copper, pour order 395): 3280,8142 3273,8135 3273,8075.46 3279,8070 3569,8070 3598,8041 3598,7762.2 3619.2,7741 3755,7741 3773.42,7760.42 3773.42,8093.58 3725,8142
AVDD on Top Layer "AVDD_L01_P394" (solid, remove dead copper, pour order 394): 3476,7723.7 3563.28,7723.7 3572,7732.42 3572,7860 3562.3,7869.7 3226,7869.7 3208,7851.7 3208,7733.89 3218.19,7723.7
NetC102_1 on Top Layer "NETC102_1_L01_P393" (solid, remove dead copper, pour order 393): 2943.46,7733.7 2938,7739.16 2938,7779.7 2944.54,7786.24 3147.46,7786.24 3151,7782.7 3151,7736.7 3148,7733.7
no net on Top Layer "NONET_L01_P392" (solid, remove dead copper, pour order 392): 2986,7739.7
5V on Top Layer "5V_L01_P391" (solid, remove dead copper, pour order 391): 2918,7871 2899,7890 2191,7890 2135.54,7834.54 1948,7834.54 1944,7830.54 1944,7785.19 1949.19,7780 2310,7780 2802,7780 2848.44,7733.56 2913.56,7733.56 2918,7738
10V on Top Layer "10V_L01_P390" (solid, remove dead copper, pour order 390): 19 vertices, not listed, extent 1362,7087.5 1859,7688
10V_Gate on Top Layer "10V_GATE_L01_P386" (solid, remove dead copper, pour order 386): 946.51,6690.21 954,6697.7 1085,6697.7 1104,6678.7 1104,6452.46 1100,6448.46 1031.54,6448.46 1030,6450 1030,6598.55 1015.5,6613.05 961.17,6613.05 946.51,6627.7
10V_Gate on Top Layer "10V_GATE_L01_P385" (solid, remove dead copper, pour order 385): 18 vertices, not listed, extent 890,7375 1550,7874.7
AGND on Top Layer "AGND_L01_P384" (solid, remove dead copper, pour order 384): 688,6331.7 700,6319.7 851,6319.7 856,6324.7 856,6420.7 866,6430.7 890,6430.7 906,6446.7 906,6478.7 894,6490.7 692,6490.7 688,6486.7
PGND on Top Layer "PGND_L01_P383" (solid, remove dead copper, pour order 383): 43 vertices, not listed, extent 521.5,5875.7 1330,7563.7
NetD10_2 on Top Layer "NETD10_2_L01_P382" (solid, remove dead copper, pour order 382): 930,7075.7 930,7335.7 944,7349.7 1060,7349.7 1067,7342.7 1067,6995.7 1059,6987.7 934.62,6987.7 930.62,6991.7 930,6992.32
NetD9_2 on Top Layer "NETD9_2_L01_P381" (solid, remove dead copper, pour order 381): 17 vertices, not listed, extent 266,7239.7 836,7886.7
NetC112_1 on Top Layer "NETC112_1_L01_P380" (solid, remove dead copper, pour order 380): 25 vertices, not listed, extent 266,6793.7 791,7349.7
PGND on Top Layer "PGND_L01_P378" (solid, remove dead copper, pour order 378): 25 vertices, not listed, extent 993,38 1556,3407
NetD5_2 on Top Layer "NETD5_2_L01_P376" (solid, remove dead copper, pour order 376): 19 vertices, not listed, extent 63,1425 781,2059
NetD5_1 on Top Layer "NETD5_1_L01_P373" (solid, remove dead copper, pour order 373): 560.14,1801 554,1794.86 554,1682 562,1674 651,1674 655,1678 655,1798 652,1801
NetD6_2 on Top Layer "NETD6_2_L01_P371" (solid, remove dead copper, pour order 371): 17 vertices, not listed, extent 687,1532 837,1814
no net on Top Layer "NONET_L01_P370" (solid, remove dead copper, pour order 370): 737,1812
NetD6_1 on Top Layer "NETD6_1_L01_P369" (solid, remove dead copper, pour order 369): 17 vertices, not listed, extent 863,1510 993,1700
NetD7_1 on Top Layer "NETD7_1_L01_P366" (solid, remove dead copper, pour order 366): 815,1451 808,1444 808,1367 820,1355 879,1355 884,1360 884,1409.86 889.14,1415 939,1415 942,1418 942,1449.07 940.07,1451
12VP on Top Layer "12VP_L01_P365" (solid, remove dead copper, pour order 365): 24 vertices, not listed, extent 377,38 957,1399
PGND on Bottom Layer "PGND_L06_P681" (solid, remove dead copper, pour order 681): 1550,8206 1550,7568.7 1472,7490.7 1472,5123 1328,4979 77,4979 38,5018 38,8187 81,8230 1526,8230
AGND on Bottom Layer "AGND_L06_P677" (solid, remove dead copper, pour order 677): 51 vertices, not listed, extent 1518,4884 14680,8230
DGND on Bottom Layer "DGND_L06_P675" (solid, remove dead copper, pour order 675): 43 vertices, not listed, extent 1590,6299.47 11480,8230
NetD5_2 on Bottom Layer "NETD5_2_L06_P582" (solid, remove dead copper, pour order 582): 20 vertices, not listed, extent 63,1425 781,2059
AGND on Bottom Layer "AGND_L06_P568" (solid, remove dead copper, pour order 568): 1437,6480 1518,6561 1518,6870 1527,6879 1660.46,6879 1678,6861.46 1678,6363.62 1632,6317.62 687.38,6317.62 671,6334 671,6454 697,6480
12VP on Bottom Layer "12VP_L06_P556" (solid, remove dead copper, pour order 556): 18 vertices, not listed, extent 377,38 957,1399
12V_Out on Bottom Layer "12V_OUT_L06_P554" (solid, remove dead copper, pour order 554): 82 vertices, not listed, extent 535,1686 13318.12,4859
PGND on Bottom Layer "PGND_L06_P544" (solid, remove dead copper, pour order 544): 25 vertices, not listed, extent 993,38 1556,3407
PGND on Bottom Layer "PGND_L06_P464" (solid, remove dead copper, pour order 464): 25 vertices, not listed, extent 13706.2,33.45 14390.7,4231.45
NetF1_Ch8_1 on Bottom Layer "NETF1_CH8_1_L06_P492" (solid, remove dead copper, pour order 492): 13558.7,1077.45 13561.7,1074.45 13561.7,886.45 13691.7,756.45 13691.7,51.45 13673.7,33.45 13014.7,33.45 13000.7,47.45 13000.7,1067.45 13010.7,1077.45
NetF1_Ch8_2 on Bottom Layer "NETF1_CH8_2_L06_P496" (solid, remove dead copper, pour order 496): 13563.7,1119.45 13572.7,1110.45 13637.7,1110.45 13648.7,1099.45 13648.7,862.45 13680.7,830.45 13948.7,830.45 13961.7,843.45 13961.7,1281.45 13951.7,1291.45 13578.7,1291.45 13563.7,1276.45
NetC3_Ch8_1 on Bottom Layer "NETC3_CH8_1_L06_P500" (solid, remove dead copper, pour order 500): 13398.13,3265.02 13409.7,3253.45 13637.7,3253.45 13646.7,3262.45 13646.7,4221.45 13636.7,4231.45 13405.7,4231.45 13398.13,4223.87
SW_Ch8 on Bottom Layer "SW_CH8_L06_P504" (solid, remove dead copper, pour order 504): 21 vertices, not listed, extent 13686.7,2477.45 14043.7,3481.45
NetL2_Ch8_2 on Bottom Layer "NETL2_CH8_2_L06_P508" (solid, remove dead copper, pour order 508): 13014.83,2889.45 13000.7,2875.32 13000.7,1823.45 13011.7,1812.45 13346.7,1812.45 13354.7,1820.45 13354.7,2111.45 13389.7,2146.45 13389.7,2882.45 13382.7,2889.45
NetC9_Ch8_1 on Bottom Layer "NETC9_CH8_1_L06_P512" (solid, remove dead copper, pour order 512): 17 vertices, not listed, extent 13513.7,1442.45 13984.7,2213.45
NetC9_Ch7_1 on Bottom Layer "NETC9_CH7_1_L06_P511" (solid, remove dead copper, pour order 511): 17 vertices, not listed, extent 11951.7,1442.53 12422.7,2213.53
NetL2_Ch7_2 on Bottom Layer "NETL2_CH7_2_L06_P507" (solid, remove dead copper, pour order 507): 11452.83,2889.53 11438.7,2875.4 11438.7,1823.53 11449.7,1812.53 11784.7,1812.53 11792.7,1820.53 11792.7,2111.53 11827.7,2146.53 11827.7,2882.53 11820.7,2889.53
SW_Ch7 on Bottom Layer "SW_CH7_L06_P503" (solid, remove dead copper, pour order 503): 21 vertices, not listed, extent 12124.7,2477.53 12481.7,3481.53
NetC3_Ch7_1 on Bottom Layer "NETC3_CH7_1_L06_P499" (solid, remove dead copper, pour order 499): 11836.13,3265.1 11847.7,3253.53 12075.7,3253.53 12084.7,3262.53 12084.7,4221.53 12074.7,4231.53 11843.7,4231.53 11836.13,4223.95
NetF1_Ch7_2 on Bottom Layer "NETF1_CH7_2_L06_P495" (solid, remove dead copper, pour order 495): 12001.7,1119.53 12010.7,1110.53 12075.7,1110.53 12086.7,1099.53 12086.7,862.53 12118.7,830.53 12386.7,830.53 12399.7,843.53 12399.7,1281.53 12389.7,1291.53 12016.7,1291.53 12001.7,1276.53
NetF1_Ch7_1 on Bottom Layer "NETF1_CH7_1_L06_P491" (solid, remove dead copper, pour order 491): 11996.7,1077.53 11999.7,1074.53 11999.7,886.53 12129.7,756.53 12129.7,51.53 12111.7,33.53 11452.7,33.53 11438.7,47.53 11438.7,1067.53 11448.7,1077.53
PGND on Bottom Layer "PGND_L06_P463" (solid, remove dead copper, pour order 463): 25 vertices, not listed, extent 12144.2,33.53 12828.7,4231.53
PGND on Bottom Layer "PGND_L06_P462" (solid, remove dead copper, pour order 462): 25 vertices, not listed, extent 10582.2,33.61 11266.7,4231.61
NetF1_Ch6_1 on Bottom Layer "NETF1_CH6_1_L06_P490" (solid, remove dead copper, pour order 490): 10434.7,1077.61 10437.7,1074.61 10437.7,886.61 10567.7,756.61 10567.7,51.61 10549.7,33.61 9890.7,33.61 9876.7,47.61 9876.7,1067.61 9886.7,1077.61
NetF1_Ch6_2 on Bottom Layer "NETF1_CH6_2_L06_P494" (solid, remove dead copper, pour order 494): 10439.7,1119.61 10448.7,1110.61 10513.7,1110.61 10524.7,1099.61 10524.7,862.61 10556.7,830.61 10824.7,830.61 10837.7,843.61 10837.7,1281.61 10827.7,1291.61 10454.7,1291.61 10439.7,1276.61
NetC3_Ch6_1 on Bottom Layer "NETC3_CH6_1_L06_P498" (solid, remove dead copper, pour order 498): 10274.13,3265.18 10285.7,3253.61 10513.7,3253.61 10522.7,3262.61 10522.7,4221.61 10512.7,4231.61 10281.7,4231.61 10274.13,4224.03
SW_Ch6 on Bottom Layer "SW_CH6_L06_P502" (solid, remove dead copper, pour order 502): 21 vertices, not listed, extent 10562.7,2477.61 10919.7,3481.61
NetL2_Ch6_2 on Bottom Layer "NETL2_CH6_2_L06_P506" (solid, remove dead copper, pour order 506): 9890.83,2889.61 9876.7,2875.48 9876.7,1823.61 9887.7,1812.61 10222.7,1812.61 10230.7,1820.61 10230.7,2111.61 10265.7,2146.61 10265.7,2882.61 10258.7,2889.61
NetC9_Ch6_1 on Bottom Layer "NETC9_CH6_1_L06_P510" (solid, remove dead copper, pour order 510): 17 vertices, not listed, extent 10389.7,1442.61 10860.7,2213.61
NetC9_Ch5_1 on Bottom Layer "NETC9_CH5_1_L06_P509" (solid, remove dead copper, pour order 509): 17 vertices, not listed, extent 8827.7,1442.69 9298.7,2213.69
NetL2_Ch5_2 on Bottom Layer "NETL2_CH5_2_L06_P505" (solid, remove dead copper, pour order 505): 8328.83,2889.68 8314.7,2875.56 8314.7,1823.69 8325.7,1812.69 8660.7,1812.69 8668.7,1820.69 8668.7,2111.69 8703.7,2146.68 8703.7,2882.69 8696.7,2889.69
SW_Ch5 on Bottom Layer "SW_CH5_L06_P501" (solid, remove dead copper, pour order 501): 21 vertices, not listed, extent 9000.7,2477.69 9357.7,3481.69
NetC3_Ch5_1 on Bottom Layer "NETC3_CH5_1_L06_P497" (solid, remove dead copper, pour order 497): 8712.13,3265.26 8723.7,3253.69 8951.7,3253.69 8960.7,3262.69 8960.7,4221.69 8950.7,4231.69 8719.7,4231.69 8712.13,4224.11
NetF1_Ch5_2 on Bottom Layer "NETF1_CH5_2_L06_P493" (solid, remove dead copper, pour order 493): 8877.7,1119.69 8886.7,1110.69 8951.7,1110.69 8962.7,1099.69 8962.7,862.69 8994.7,830.69 9262.7,830.69 9275.7,843.69 9275.7,1281.69 9265.7,1291.69 8892.7,1291.69 8877.7,1276.69
NetF1_Ch5_1 on Bottom Layer "NETF1_CH5_1_L06_P489" (solid, remove dead copper, pour order 489): 8872.7,1077.69 8875.7,1074.69 8875.7,886.69 9005.7,756.69 9005.7,51.69 8987.7,33.69 8328.7,33.69 8314.7,47.69 8314.7,1067.69 8324.7,1077.69
PGND on Bottom Layer "PGND_L06_P461" (solid, remove dead copper, pour order 461): 25 vertices, not listed, extent 9020.2,33.69 9704.7,4231.69
NetF1_Ch4_1 on Bottom Layer "NETF1_CH4_1_L06_P408" (solid, remove dead copper, pour order 408): 6917,1077.76 6920,1074.76 6920,886.76 7050,756.76 7050,51.76 7032,33.76 6373,33.76 6359,47.76 6359,1067.76 6369,1077.76
NetF1_Ch4_2 on Bottom Layer "NETF1_CH4_2_L06_P416" (solid, remove dead copper, pour order 416): 6922,1119.76 6931,1110.76 6996,1110.76 7007,1099.76 7007,862.76 7039,830.76 7307,830.76 7320,843.76 7320,1281.76 7310,1291.76 6937,1291.76 6922,1276.76
NetC3_Ch4_1 on Bottom Layer "NETC3_CH4_1_L06_P424" (solid, remove dead copper, pour order 424): 6756.43,3265.34 6768,3253.76 6996,3253.76 7005,3262.76 7005,4221.76 6995,4231.76 6764,4231.76 6756.43,4224.19
SW_Ch4 on Bottom Layer "SW_CH4_L06_P432" (solid, remove dead copper, pour order 432): 21 vertices, not listed, extent 7045,2477.76 7402,3481.76
NetL2_Ch4_2 on Bottom Layer "NETL2_CH4_2_L06_P440" (solid, remove dead copper, pour order 440): 6373.13,2889.76 6359,2875.64 6359,1823.76 6370,1812.76 6705,1812.76 6713,1820.76 6713,2111.76 6748,2146.76 6748,2882.76 6741,2889.76
NetC9_Ch4_1 on Bottom Layer "NETC9_CH4_1_L06_P448" (solid, remove dead copper, pour order 448): 17 vertices, not listed, extent 6872,1442.76 7343,2213.76
PGND on Bottom Layer "PGND_L06_P456" (solid, remove dead copper, pour order 456): 25 vertices, not listed, extent 7064.5,33.76 7749,4231.76
PGND on Bottom Layer "PGND_L06_P455" (solid, remove dead copper, pour order 455): 25 vertices, not listed, extent 5502.5,33.84 6187,4231.84
NetC9_Ch3_1 on Bottom Layer "NETC9_CH3_1_L06_P447" (solid, remove dead copper, pour order 447): 17 vertices, not listed, extent 5310,1442.84 5781,2213.84
NetL2_Ch3_2 on Bottom Layer "NETL2_CH3_2_L06_P439" (solid, remove dead copper, pour order 439): 4811.13,2889.84 4797,2875.71 4797,1823.84 4808,1812.84 5143,1812.84 5151,1820.84 5151,2111.84 5186,2146.84 5186,2882.84 5179,2889.84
